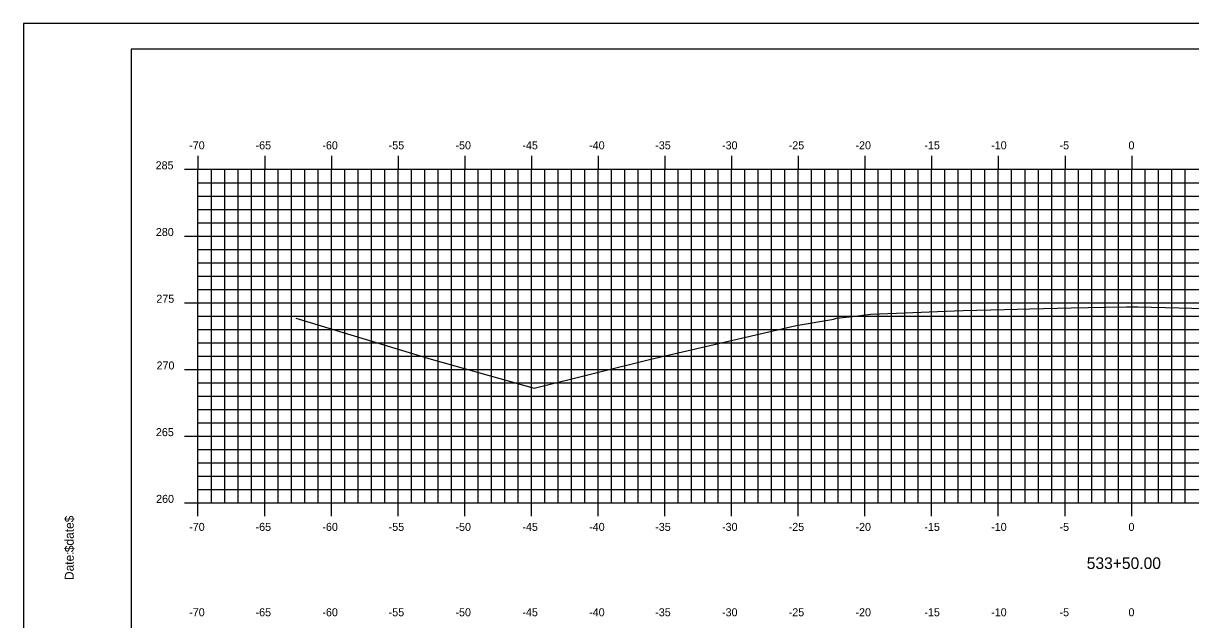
# Model space of a CAD drawing. Extents: x 1170543 to 1177585, y 609599 to 610623.
# Drawn here: x 1176604.5 to 1176692, y 609664.1 to 609708.8 of the extents above; entities that cross this region are included whole.
import ezdxf

# ---------------------------------------------------------------- set-up
doc = ezdxf.new("R2010")
doc.units = 0
for name, color, linetype in [('BORDER', 7, 'Continuous'), ('H_V ANNOTATION', 7, 'Continuous'), ('MAJOR', 7, 'Continuous'), ('MINOR', 7, 'Continuous'), ('PLOT BOUNDARY', 7, 'Continuous'), ('S_Roadway_Centerline', 7, 'Continuous')]:
    doc.layers.add(name, color=color, linetype=linetype)

msp = doc.modelspace()

# ---------------------------------------------------------------- linework, layer by layer
at = {"layer": 'BORDER'}
for p, q in [((1176772.609, 609706.872), (1176612.609, 609706.872)), ((1176612.609, 609706.872), (1176612.609, 609601.872))]:
    msp.add_line(p, q, dxfattribs=at)
at = {"layer": 'MAJOR'}
for p, q in [((1176617.609, 609698.874), (1176617.609, 609697.872)), ((1176622.609, 609698.874), (1176622.609, 609697.872)), ((1176627.609, 609698.874), (1176627.609, 609697.872)), ((1176632.609, 609698.874), (1176632.609, 609697.872)), ((1176637.609, 609698.874), (1176637.609, 609697.872)), ((1176642.609, 609698.874), (1176642.609, 609697.872)), ((1176647.609, 609698.874), (1176647.609, 609697.872)), ((1176652.609, 609698.874), (1176652.609, 609697.872)), ((1176657.609, 609698.874), (1176657.609, 609697.872)), ((1176662.609, 609698.874), (1176662.609, 609697.872)), ((1176667.609, 609698.874), (1176667.609, 609697.872)), ((1176672.609, 609698.874), (1176672.609, 609697.872)), ((1176677.609, 609698.874), (1176677.609, 609697.872)), ((1176682.609, 609698.874), (1176682.609, 609697.872)), ((1176687.609, 609698.874), (1176687.609, 609697.872)), ((1176616.607, 609697.872), (1176617.609, 609697.872)), ((1176617.609, 609697.872), (1176757.609, 609697.872)), ((1176617.609, 609672.872), (1176617.609, 609697.872)), ((1176617.609, 609672.872), (1176617.609, 609697.872)), ((1176617.609, 609697.872), (1176757.609, 609697.872)), ((1176622.609, 609672.872), (1176622.609, 609697.872)), ((1176627.609, 609672.872), (1176627.609, 609697.872)), ((1176632.609, 609672.872), (1176632.609, 609697.872)), ((1176637.609, 609672.872), (1176637.609, 609697.872)), ((1176642.609, 609672.872), (1176642.609, 609697.872)), ((1176647.609, 609672.872), (1176647.609, 609697.872)), ((1176652.609, 609672.872), (1176652.609, 609697.872)), ((1176657.609, 609672.872), (1176657.609, 609697.872)), ((1176662.609, 609672.872), (1176662.609, 609697.872)), ((1176667.609, 609672.872), (1176667.609, 609697.872)), ((1176672.609, 609672.872), (1176672.609, 609697.872)), ((1176677.609, 609672.872), (1176677.609, 609697.872)), ((1176682.609, 609672.872), (1176682.609, 609697.872)), ((1176687.609, 609672.872), (1176687.609, 609697.872)), ((1176616.607, 609692.872), (1176617.609, 609692.872)), ((1176617.609, 609692.872), (1176757.609, 609692.872)), ((1176616.607, 609687.872), (1176617.609, 609687.872)), ((1176617.609, 609687.872), (1176757.609, 609687.872)), ((1176616.607, 609682.872), (1176617.609, 609682.872)), ((1176617.609, 609682.872), (1176757.609, 609682.872)), ((1176616.607, 609677.872), (1176617.609, 609677.872)), ((1176617.609, 609677.872), (1176757.609, 609677.872)), ((1176616.607, 609672.872), (1176617.609, 609672.872)), ((1176617.609, 609672.872), (1176757.609, 609672.872)), ((1176617.609, 609672.872), (1176757.609, 609672.872)), ((1176617.609, 609671.87), (1176617.609, 609672.872)), ((1176622.609, 609671.87), (1176622.609, 609672.872)), ((1176627.609, 609671.87), (1176627.609, 609672.872)), ((1176632.609, 609671.87), (1176632.609, 609672.872)), ((1176637.609, 609671.87), (1176637.609, 609672.872)), ((1176642.609, 609671.87), (1176642.609, 609672.872)), ((1176647.609, 609671.87), (1176647.609, 609672.872)), ((1176652.609, 609671.87), (1176652.609, 609672.872)), ((1176657.609, 609671.87), (1176657.609, 609672.872)), ((1176662.609, 609671.87), (1176662.609, 609672.872)), ((1176667.609, 609671.87), (1176667.609, 609672.872)), ((1176672.609, 609671.87), (1176672.609, 609672.872)), ((1176677.609, 609671.87), (1176677.609, 609672.872)), ((1176682.609, 609671.87), (1176682.609, 609672.872)), ((1176687.609, 609671.87), (1176687.609, 609672.872))]:
    msp.add_line(p, q, dxfattribs=at)
at = {"layer": 'MINOR'}
for p, q in [((1176618.609, 609672.872), (1176618.609, 609697.872)), ((1176619.609, 609672.872), (1176619.609, 609697.872)), ((1176620.609, 609672.872), (1176620.609, 609697.872)), ((1176621.609, 609672.872), (1176621.609, 609697.872)), ((1176623.609, 609672.872), (1176623.609, 609697.872)), ((1176624.609, 609672.872), (1176624.609, 609697.872)), ((1176625.609, 609672.872), (1176625.609, 609697.872)), ((1176626.609, 609672.872), (1176626.609, 609697.872)), ((1176628.609, 609672.872), (1176628.609, 609697.872)), ((1176629.609, 609672.872), (1176629.609, 609697.872)), ((1176630.609, 609672.872), (1176630.609, 609697.872)), ((1176631.609, 609672.872), (1176631.609, 609697.872)), ((1176633.609, 609672.872), (1176633.609, 609697.872)), ((1176634.609, 609672.872), (1176634.609, 609697.872)), ((1176635.609, 609672.872), (1176635.609, 609697.872)), ((1176636.609, 609672.872), (1176636.609, 609697.872)), ((1176638.609, 609672.872), (1176638.609, 609697.872)), ((1176639.609, 609672.872), (1176639.609, 609697.872)), ((1176640.609, 609672.872), (1176640.609, 609697.872)), ((1176641.609, 609672.872), (1176641.609, 609697.872)), ((1176643.609, 609672.872), (1176643.609, 609697.872)), ((1176644.609, 609672.872), (1176644.609, 609697.872)), ((1176645.609, 609672.872), (1176645.609, 609697.872)), ((1176646.609, 609672.872), (1176646.609, 609697.872)), ((1176648.609, 609672.872), (1176648.609, 609697.872)), ((1176649.609, 609672.872), (1176649.609, 609697.872)), ((1176650.609, 609672.872), (1176650.609, 609697.872)), ((1176651.609, 609672.872), (1176651.609, 609697.872)), ((1176653.609, 609672.872), (1176653.609, 609697.872)), ((1176654.609, 609672.872), (1176654.609, 609697.872)), ((1176655.609, 609672.872), (1176655.609, 609697.872)), ((1176656.609, 609672.872), (1176656.609, 609697.872)), ((1176658.609, 609672.872), (1176658.609, 609697.872)), ((1176659.609, 609672.872), (1176659.609, 609697.872)), ((1176660.609, 609672.872), (1176660.609, 609697.872)), ((1176661.609, 609672.872), (1176661.609, 609697.872)), ((1176663.609, 609672.872), (1176663.609, 609697.872)), ((1176664.609, 609672.872), (1176664.609, 609697.872)), ((1176665.609, 609672.872), (1176665.609, 609697.872)), ((1176666.609, 609672.872), (1176666.609, 609697.872)), ((1176668.609, 609672.872), (1176668.609, 609697.872)), ((1176669.609, 609672.872), (1176669.609, 609697.872)), ((1176670.609, 609672.872), (1176670.609, 609697.872)), ((1176671.609, 609672.872), (1176671.609, 609697.872)), ((1176673.609, 609672.872), (1176673.609, 609697.872)), ((1176674.609, 609672.872), (1176674.609, 609697.872)), ((1176675.609, 609672.872), (1176675.609, 609697.872)), ((1176676.609, 609672.872), (1176676.609, 609697.872)), ((1176678.609, 609672.872), (1176678.609, 609697.872)), ((1176679.609, 609672.872), (1176679.609, 609697.872)), ((1176680.609, 609672.872), (1176680.609, 609697.872)), ((1176681.609, 609672.872), (1176681.609, 609697.872)), ((1176683.609, 609672.872), (1176683.609, 609697.872)), ((1176684.609, 609672.872), (1176684.609, 609697.872)), ((1176685.609, 609672.872), (1176685.609, 609697.872)), ((1176686.609, 609672.872), (1176686.609, 609697.872)), ((1176688.609, 609672.872), (1176688.609, 609697.872)), ((1176689.609, 609672.872), (1176689.609, 609697.872)), ((1176690.609, 609672.872), (1176690.609, 609697.872)), ((1176691.609, 609672.872), (1176691.609, 609697.872)), ((1176617.609, 609696.872), (1176757.609, 609696.872)), ((1176617.609, 609696.872), (1176618.611, 609696.872)), ((1176617.609, 609695.872), (1176757.609, 609695.872)), ((1176617.609, 609695.872), (1176618.611, 609695.872)), ((1176617.609, 609694.872), (1176757.609, 609694.872)), ((1176617.609, 609694.872), (1176618.611, 609694.872)), ((1176617.609, 609693.872), (1176757.609, 609693.872)), ((1176617.609, 609693.872), (1176618.611, 609693.872)), ((1176617.609, 609691.872), (1176757.609, 609691.872)), ((1176617.609, 609691.872), (1176618.611, 609691.872)), ((1176617.609, 609690.872), (1176757.609, 609690.872)), ((1176617.609, 609690.872), (1176618.611, 609690.872)), ((1176617.609, 609689.872), (1176757.609, 609689.872)), ((1176617.609, 609689.872), (1176618.611, 609689.872)), ((1176617.609, 609688.872), (1176757.609, 609688.872)), ((1176617.609, 609688.872), (1176618.611, 609688.872)), ((1176617.609, 609686.872), (1176757.609, 609686.872)), ((1176617.609, 609686.872), (1176618.611, 609686.872)), ((1176617.609, 609685.872), (1176757.609, 609685.872)), ((1176617.609, 609685.872), (1176618.611, 609685.872)), ((1176617.609, 609684.872), (1176757.609, 609684.872)), ((1176617.609, 609684.872), (1176618.611, 609684.872)), ((1176617.609, 609683.872), (1176757.609, 609683.872)), ((1176617.609, 609683.872), (1176618.611, 609683.872)), ((1176617.609, 609681.872), (1176757.609, 609681.872)), ((1176617.609, 609681.872), (1176618.611, 609681.872)), ((1176617.609, 609680.872), (1176757.609, 609680.872)), ((1176617.609, 609680.872), (1176618.611, 609680.872)), ((1176617.609, 609679.872), (1176757.609, 609679.872)), ((1176617.609, 609679.872), (1176618.611, 609679.872)), ((1176617.609, 609678.872), (1176757.609, 609678.872)), ((1176617.609, 609678.872), (1176618.611, 609678.872)), ((1176617.609, 609676.872), (1176757.609, 609676.872)), ((1176617.609, 609676.872), (1176618.611, 609676.872)), ((1176617.609, 609675.872), (1176757.609, 609675.872)), ((1176617.609, 609675.872), (1176618.611, 609675.872)), ((1176617.609, 609674.872), (1176757.609, 609674.872)), ((1176617.609, 609674.872), (1176618.611, 609674.872)), ((1176617.609, 609673.872), (1176757.609, 609673.872)), ((1176617.609, 609673.872), (1176618.611, 609673.872))]:
    msp.add_line(p, q, dxfattribs=at)
at = {"layer": 'PLOT BOUNDARY'}
msp.add_lwpolyline([(1176604.516, 609598.813), (1176774.516, 609598.813), (1176774.516, 609708.813), (1176604.516, 609708.813)], close=True, dxfattribs=at)
at = {"layer": 'S_Roadway_Centerline'}
msp.add_lwpolyline([(1176624.937, 609686.721), (1176635.101, 609683.647), (1176642.814, 609681.479), (1176651.56, 609683.633), (1176662.457, 609686.156), (1176665.274, 609686.643), (1176665.452, 609686.721), (1176666.679, 609686.833), (1176668.061, 609687.013), (1176669.971, 609687.092), (1176673.061, 609687.222), (1176674.97, 609687.279), (1176678.061, 609687.371), (1176679.969, 609687.418), (1176683.061, 609687.496), (1176685.63, 609687.545), (1176687.219, 609687.576), (1176687.745, 609687.567), (1176688.061, 609687.565), (1176691.161, 609687.493), (1176693.061, 609687.446)], dxfattribs=at)

# ---------------------------------------------------------------- texts
at = {"layer": 'BORDER'}
for s, p in [('$date$', (1176608.294, 609669.177)), ('Date:', (1176608.294, 609667.089))]:
    msp.add_text(s, height=0.6696, rotation=90, dxfattribs=at).set_placement(p)
at = {"layer": 'H_V ANNOTATION'}
for s, height, p in [('-70', 0.6, (1176616.95, 609699.372)), ('-65', 0.6, (1176621.927, 609699.372)), ('-60', 0.6, (1176626.935, 609699.372)), ('-55', 0.6, (1176631.905, 609699.372)), ('-50', 0.6, (1176636.913, 609699.372)), ('-45', 0.6, (1176641.927, 609699.372)), ('-40', 0.6, (1176646.935, 609699.372)), ('-35', 0.6, (1176651.889, 609699.372)), ('-30', 0.6, (1176656.897, 609699.372)), ('-25', 0.6, (1176661.894, 609699.372)), ('-20', 0.6, (1176666.902, 609699.372)), ('-15', 0.6, (1176672.066, 609699.372)), ('-10', 0.6, (1176677.074, 609699.372)), ('-5', 0.6, (1176682.199, 609699.372)), ('0', 0.6, (1176687.368, 609699.372)), ('285', 0.6, (1176614.433, 609697.872)), ('280', 0.6, (1176614.45, 609692.872)), ('275', 0.6, (1176614.487, 609687.872)), ('270', 0.6, (1176614.503, 609682.872)), ('265', 0.6, (1176614.455, 609677.872)), ('260', 0.6, (1176614.471, 609672.872)), ('-70', 0.6, (1176616.95, 609670.772)), ('-65', 0.6, (1176621.927, 609670.772)), ('-60', 0.6, (1176626.935, 609670.772)), ('-55', 0.6, (1176631.905, 609670.772)), ('-50', 0.6, (1176636.913, 609670.772)), ('-45', 0.6, (1176641.927, 609670.772)), ('-40', 0.6, (1176646.935, 609670.772)), ('-35', 0.6, (1176651.889, 609670.772)), ('-30', 0.6, (1176656.897, 609670.772)), ('-25', 0.6, (1176661.894, 609670.772)), ('-20', 0.6, (1176666.902, 609670.772)), ('-15', 0.6, (1176672.066, 609670.772)), ('-10', 0.6, (1176677.074, 609670.772)), ('-5', 0.6, (1176682.199, 609670.772)), ('0', 0.6, (1176687.368, 609670.772)), ('533+50.00', 0.875, (1176684.238, 609667.915)), ('-70', 0.6, (1176616.95, 609664.372)), ('-65', 0.6, (1176621.927, 609664.372)), ('-60', 0.6, (1176626.935, 609664.372)), ('-55', 0.6, (1176631.905, 609664.372)), ('-50', 0.6, (1176636.913, 609664.372)), ('-45', 0.6, (1176641.927, 609664.372)), ('-40', 0.6, (1176646.935, 609664.372)), ('-35', 0.6, (1176651.889, 609664.372)), ('-30', 0.6, (1176656.897, 609664.372)), ('-25', 0.6, (1176661.894, 609664.372)), ('-20', 0.6, (1176666.902, 609664.372)), ('-15', 0.6, (1176672.066, 609664.372)), ('-10', 0.6, (1176677.074, 609664.372)), ('-5', 0.6, (1176682.199, 609664.372)), ('0', 0.6, (1176687.368, 609664.372))]:
    msp.add_text(s, height=height, dxfattribs=at).set_placement(p)

doc.saveas('drawing.dxf')
